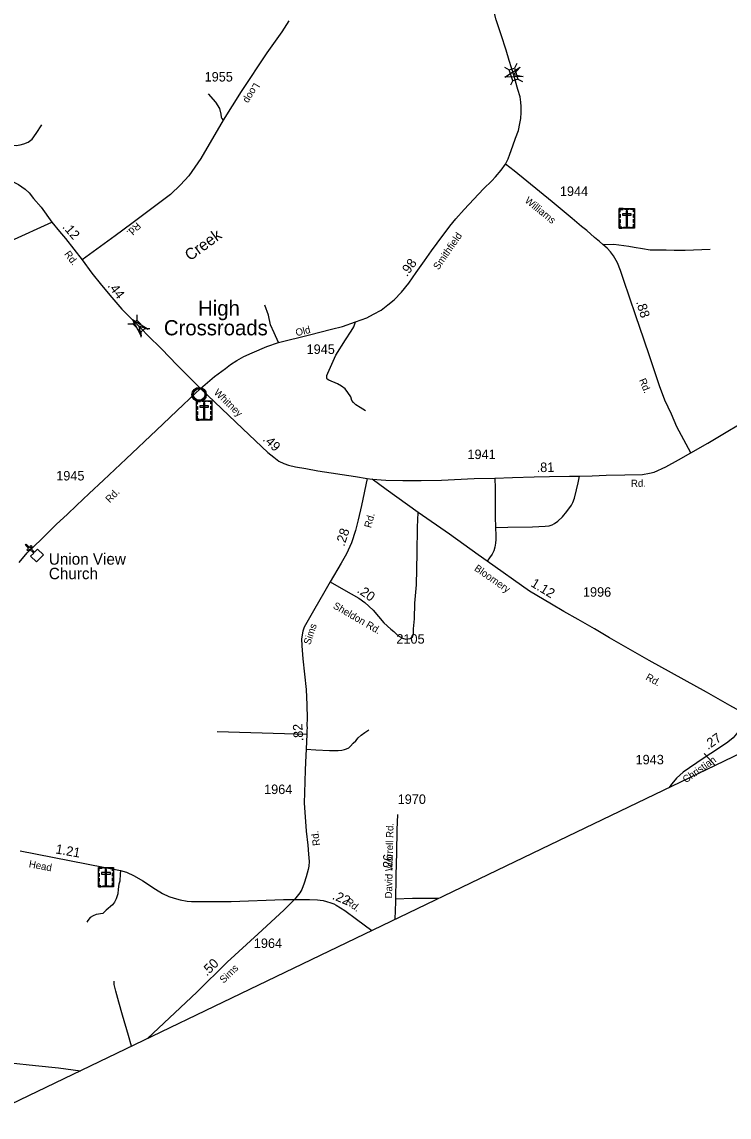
# Model space of a CAD drawing. Extents: x 2220236 to 2384410, y 720751 to 894131.
# Drawn here: x 2280691 to 2290003, y 740481 to 754902 of the extents above; entities that cross this region are included whole.
import ezdxf

# ---------------------------------------------------------------- set-up
doc = ezdxf.new("R2010")
doc.units = 0
doc.layers.add('Default', color=7, linetype='Continuous')

msp = doc.modelspace()

# ---------------------------------------------------------------- linework, layer by layer
at = {"layer": 'Default'}
for p, q in [((2287208, 754355), (2287177, 754294)), ((2287048, 754304), (2287109, 754272)), ((2287156, 754129), (2287124, 754067)), ((2287222, 754149), (2287283, 754118)), ((2282205, 751045), (2282204, 750976)), ((2282084, 750928), (2282153, 750927)), ((2282258, 750818), (2282256, 750749)), ((2282308, 750866), (2282377, 750865)), ((2285239, 748892), (2285304, 748879)), ((2289822, 745112), (2289673, 745271))]:
    msp.add_line(p, q, dxfattribs=at)
for points in [[(2287167, 754200), (2287109, 754392), (2287067, 754530), (2287001, 754731), (2286937, 754931), (2286870, 755191), (2286839, 755296), (2286815, 755396), (2286813, 755443), (2286806, 755503), (2286807, 755601), (2286821, 755780), (2286830, 755912), (2286851, 756119), (2286870, 756313), (2286881, 756471), (2286894, 756654), (2286896, 756785), (2286893, 756867), (2286868, 756978)], [(2284206, 754915), (2284114, 754770), (2283915, 754493), (2283577, 753984), (2283342, 753606), (2283049, 753103), (2282887, 752873), (2282780, 752756), (2282646, 752630), (2282140, 752249), (2281917, 752084), (2281486, 751771)], [(2287060, 753028), (2287094, 753101), (2287116, 753161), (2287156, 753269), (2287191, 753372), (2287229, 753470), (2287248, 753563), (2287261, 753630), (2287267, 753708), (2287265, 753790), (2287263, 753847), (2287250, 753917), (2287223, 754012), (2287167, 754200)], [(2283145, 753956), (2283242, 753845), (2283291, 753763), (2283309, 753687), (2283314, 753649), (2283324, 753628), (2283342, 753606)], [(2279960, 753282), (2280113, 753275), (2280189, 753286), (2280510, 753285), (2280616, 753276), (2280670, 753285), (2280718, 753295), (2280774, 753320), (2280824, 753358), (2280879, 753433), (2280954, 753547)], [(2279912, 753102), (2280529, 752822), (2280647, 752763), (2280736, 752699), (2280788, 752652), (2280842, 752575), (2280945, 752462), (2281085, 752263)], [(2283042, 750077), (2283228, 750231), (2283374, 750339), (2283440, 750391), (2283523, 750445), (2283613, 750497), (2283721, 750545), (2283918, 750627), (2284070, 750679), (2284479, 750782), (2284766, 750856), (2284914, 750892), (2285085, 750954), (2285231, 751004), (2285323, 751052), (2285423, 751106), (2285510, 751176), (2285592, 751242), (2285690, 751343), (2285784, 751463), (2285881, 751601), (2285993, 751755), (2286083, 751886), (2286161, 751988), (2286324, 752211), (2286405, 752309), (2286514, 752433), (2286770, 752704), (2286879, 752809), (2286926, 752860), (2287003, 752950), (2287060, 753028)], [(2289498, 749227), (2289317, 749571), (2289243, 749736), (2289155, 749922), (2289087, 750112), (2289027, 750295), (2288958, 750493), (2288880, 750725), (2288776, 751030), (2288694, 751277), (2288618, 751495), (2288574, 751629), (2288533, 751731), (2288479, 751820), (2288443, 751876), (2288399, 751924), (2288340, 751973), (2288296, 752009), (2288230, 752065), (2288131, 752154), (2288061, 752210), (2287937, 752314), (2287673, 752532), (2287171, 752943), (2287060, 753028)], [(2278224, 750919), (2278785, 751188), (2279193, 751386), (2280546, 752020), (2281085, 752263)], [(2281085, 752263), (2281184, 752142), (2281266, 752048), (2281486, 751771)], [(2288340, 751973), (2288485, 751975), (2288685, 751948), (2288755, 751938), (2288861, 751918), (2288965, 751901), (2289046, 751902), (2289174, 751900), (2289279, 751896), (2289423, 751898), (2289755, 751909)], [(2281486, 751771), (2281611, 751595), (2281740, 751435), (2281876, 751275), (2282009, 751118), (2282171, 750956), (2282265, 750860)], [(2284070, 750679), (2284014, 750806), (2283966, 750912), (2283938, 751042), (2283892, 751172)], [(2285215, 749783), (2285145, 749823), (2285090, 749860), (2285058, 749890), (2285036, 749916), (2285021, 749965), (2284985, 750023), (2284946, 750071), (2284900, 750104), (2284846, 750138), (2284731, 750183), (2284711, 750198), (2284705, 750212), (2284707, 750244), (2284719, 750278), (2284826, 750513), (2284954, 750717), (2285028, 750828), (2285063, 750886), (2285085, 750954)], [(2282265, 750860), (2282350, 750772), (2282528, 750599), (2282737, 750383), (2282952, 750167), (2283042, 750077)], [(2289498, 749227), (2289722, 749357), (2289923, 749475), (2290172, 749623), (2290408, 749756), (2290801, 749958), (2290961, 750056), (2291175, 750186), (2291342, 750283), (2291540, 750397), (2291661, 750471), (2291765, 750531), (2291859, 750573), (2291955, 750611), (2292119, 750666), (2292274, 750715)], [(2300140, 750264), (2297549, 748943), (2296605, 748443), (2294139, 747191), (2294129, 747181), (2290621, 745496), (2287877, 744178), (2270992, 736056), (2267562, 734406), (2264815, 733083), (2261891, 731668), (2260094, 730805), (2259694, 730607), (2256472, 729070), (2253954, 727878), (2253181, 727508), (2253078, 727457), (2253042, 727443), (2252978, 727424), (2252870, 727387), (2251763, 727086), (2250517, 726735), (2250148, 726626), (2248127, 726061)], [(2280656, 747785), (2280762, 747909), (2280948, 748092), (2281144, 748283), (2281293, 748422), (2281411, 748534), (2281576, 748691), (2281764, 748867), (2282065, 749149), (2282464, 749526), (2282820, 749866), (2283042, 750077)], [(2283042, 750077), (2283601, 749542), (2283930, 749233), (2284010, 749169), (2284075, 749120), (2284139, 749088), (2284201, 749066), (2284293, 749042), (2284428, 749020), (2284586, 748992), (2285083, 748916), (2285239, 748892)], [(2285304, 748879), (2285483, 748868), (2285709, 748862), (2285949, 748865), (2286215, 748869), (2286648, 748890), (2286919, 748896), (2287153, 748904), (2287438, 748910), (2287638, 748914), (2287902, 748920), (2288034, 748922), (2288201, 748926), (2288385, 748934), (2288631, 748936), (2288862, 748944), (2288956, 748960), (2289015, 748974), (2289169, 749044), (2289337, 749134), (2289498, 749227)], [(2285239, 748892), (2285162, 748534), (2285119, 748347), (2285085, 748203), (2285033, 748042), (2284965, 747899), (2284895, 747775), (2284750, 747528)], [(2290284, 745750), (2290015, 745902), (2289704, 746075), (2288953, 746493), (2288428, 746792), (2288232, 746910), (2288015, 747034), (2287828, 747137), (2287664, 747233), (2287377, 747407), (2286817, 747803), (2286700, 747886), (2286321, 748155), (2285909, 748443), (2285488, 748743), (2285304, 748879)], [(2286919, 748896), (2286921, 748762), (2286925, 748383), (2286929, 748243)], [(2286929, 748243), (2287088, 748249), (2287415, 748255), (2287581, 748263), (2287635, 748267), (2287673, 748279), (2287705, 748299), (2287749, 748327), (2287808, 748385), (2287866, 748457), (2287926, 748539), (2287944, 748575), (2287966, 748631), (2287994, 748742), (2288018, 748834), (2288034, 748922)], [(2285587, 746874), (2285643, 746824), (2285703, 746786), (2285747, 746774), (2285805, 746784), (2285834, 746806), (2285843, 746830), (2285847, 746854), (2285847, 746910), (2285859, 747042), (2285867, 747249), (2285885, 747489), (2285895, 747908), (2285901, 748247), (2285909, 748443)], [(2286929, 748243), (2286932, 748141), (2286930, 748088), (2286926, 748038), (2286920, 747984), (2286904, 747938), (2286882, 747892), (2286848, 747846), (2286817, 747803)], [(2284750, 747528), (2284680, 747405), (2284531, 747146), (2284443, 746993), (2284408, 746933), (2284391, 746881), (2284373, 746779), (2284378, 746688), (2284391, 746517), (2284433, 746112), (2284445, 745909), (2284447, 745730), (2284445, 745644), (2284447, 745604), (2284445, 745575), (2284441, 745523), (2284434, 745325), (2284431, 745244), (2284421, 745053), (2284417, 744897), (2284409, 744617), (2284419, 744435), (2284435, 744246), (2284455, 744061), (2284463, 743943), (2284473, 743848), (2284471, 743786), (2284461, 743740), (2284435, 743647), (2284407, 743563), (2284376, 743479), (2284352, 743436), (2284280, 743346)], [(2284750, 747528), (2284927, 747429), (2285126, 747313), (2285208, 747255), (2285318, 747155), (2285455, 746988), (2285551, 746906), (2285587, 746874)], [(2290284, 745750), (2290222, 745676), (2290164, 745606), (2290103, 745530), (2290055, 745477), (2289987, 745419), (2289863, 745333), (2289664, 745201), (2289398, 745021), (2289309, 744942), (2289271, 744898), (2289245, 744866), (2289216, 744821)], [(2283263, 745559), (2283704, 745547), (2284441, 745523)], [(2284434, 745325), (2284560, 745319), (2284740, 745309), (2284854, 745307), (2284903, 745311), (2284941, 745321), (2284967, 745329), (2284995, 745343), (2285019, 745367), (2285055, 745405), (2285087, 745437), (2285121, 745475), (2285159, 745509), (2285207, 745547), (2285259, 745579)], [(2285607, 743086), (2285616, 743316), (2285620, 743669), (2285628, 743962), (2285633, 744266), (2285643, 744466)], [(2280670, 743988), (2281988, 743730), (2282070, 743706), (2282169, 743659), (2282282, 743593), (2282451, 743481), (2282541, 743424), (2282625, 743386), (2282698, 743365), (2282774, 743340), (2282866, 743324), (2282926, 743318), (2283029, 743318), (2283121, 743318), (2283270, 743320), (2283448, 743322), (2284136, 743348), (2284192, 743346), (2284280, 743346)], [(2281988, 743730), (2281986, 743681), (2281984, 743651), (2281982, 743621), (2281979, 743586), (2281969, 743550), (2281960, 743484), (2281956, 743420), (2281933, 743356), (2281911, 743311), (2281886, 743277), (2281800, 743205), (2281767, 743172), (2281755, 743164), (2281667, 743149), (2281629, 743133), (2281590, 743109), (2281560, 743072), (2281544, 743048)], [(2284280, 743346), (2284206, 743272), (2284140, 743207), (2283803, 742894), (2283395, 742521), (2282995, 742127), (2282343, 741516)], [(2284280, 743346), (2284476, 743348), (2284582, 743343), (2284619, 743339), (2284658, 743333), (2284704, 743322), (2284759, 743304), (2284797, 743288), (2284831, 743270), (2284944, 743203), (2285098, 743089), (2285299, 742938)], [(2286176, 743361), (2285833, 743358), (2285611, 743350)], [(2282134, 741415), (2282095, 741555), (2282015, 741824), (2281967, 741996), (2281927, 742141), (2281906, 742227), (2281904, 742273)], [(2280541, 741195), (2280872, 741161), (2281172, 741130), (2281462, 741092)]]:
    msp.add_lwpolyline(points, dxfattribs=at)
for points in [[(2287292, 754184), (2287049, 754173), (2287254, 754304), (2287165, 754210)], [(2287177, 754294), (2287222, 754150), (2287155, 754128), (2287109, 754272)], [(2288557, 752443), (2288756, 752443), (2288756, 752188), (2288557, 752188)], [(2288557, 752399), (2288568, 752399), (2288568, 752432), (2288609, 752432), (2288609, 752443), (2288557, 752443)], [(2288557, 752325), (2288557, 752369), (2288568, 752369), (2288568, 752325)], [(2288598, 752375), (2288598, 752356), (2288715, 752356), (2288715, 752375)], [(2288631, 752443), (2288683, 752443), (2288683, 752431), (2288631, 752431)], [(2288666, 752413), (2288647, 752413), (2288647, 752211), (2288666, 752211)], [(2288756, 752399), (2288745, 752399), (2288745, 752432), (2288704, 752432), (2288704, 752443), (2288756, 752443)], [(2288744, 752326), (2288744, 752370), (2288756, 752370), (2288756, 752326)], [(2288557, 752258), (2288557, 752301), (2288568, 752301), (2288568, 752258)], [(2288590, 752188), (2288590, 752200), (2288568, 752200), (2288568, 752240), (2288557, 752240), (2288557, 752188)], [(2288614, 752200), (2288699, 752200), (2288699, 752188), (2288614, 752188)], [(2288723, 752188), (2288723, 752200), (2288745, 752200), (2288745, 752240), (2288756, 752240), (2288756, 752188)], [(2288744, 752260), (2288744, 752304), (2288756, 752304), (2288756, 752260)], [(2282261, 750769), (2282148, 750985), (2282354, 750855), (2282230, 750895)], [(2282204, 750976), (2282308, 750866), (2282257, 750818), (2282153, 750927)], [(2282948, 750008), (2282949, 750013), (2282950, 750020), (2282953, 750027), (2282956, 750033), (2282960, 750039), (2282963, 750044), (2282967, 750048), (2282972, 750053), (2282977, 750057), (2282983, 750061), (2282988, 750064), (2282993, 750066), (2282998, 750069), (2283004, 750070), (2283008, 750072), (2283013, 750072), (2283017, 750073), (2283024, 750073), (2283028, 750073), (2283034, 750073), (2283039, 750072), (2283044, 750071), (2283049, 750070), (2283054, 750068), (2283060, 750065), (2283067, 750061), (2283072, 750058), (2283077, 750054), (2283080, 750051), (2283084, 750046), (2283088, 750042), (2283091, 750037), (2283094, 750032), (2283097, 750027), (2283099, 750022), (2283100, 750017), (2283102, 750012), (2283103, 750006), (2283103, 750002), (2283104, 749996), (2283103, 749990), (2283103, 749984), (2283102, 749979), (2283100, 749972), (2283098, 749967), (2283096, 749962), (2283093, 749956), (2283090, 749950), (2283086, 749946), (2283082, 749941), (2283077, 749936), (2283072, 749932), (2283067, 749928), (2283062, 749926), (2283056, 749923), (2283048, 749920), (2283042, 749918), (2283036, 749917), (2283031, 749917), (2283027, 749916), (2283021, 749916), (2283017, 749917), (2283011, 749917), (2283006, 749919), (2283001, 749920), (2282996, 749922), (2282991, 749924), (2282987, 749926), (2282980, 749930), (2282975, 749935), (2282970, 749939), (2282966, 749944), (2282962, 749948), (2282959, 749952), (2282955, 749959), (2282954, 749963), (2282952, 749967), (2282949, 749975), (2282948, 749982), (2282947, 749987), (2282947, 749993), (2282947, 749998), (2282947, 750005)], [(2282991, 749914), (2283190, 749914), (2283190, 749660), (2282991, 749660)], [(2282991, 749871), (2283002, 749871), (2283002, 749903), (2283043, 749903), (2283043, 749914), (2282991, 749914)], [(2283065, 749914), (2283117, 749914), (2283117, 749903), (2283065, 749903)], [(2283100, 749885), (2283081, 749885), (2283081, 749682), (2283100, 749682)], [(2283190, 749871), (2283179, 749871), (2283179, 749903), (2283138, 749903), (2283138, 749914), (2283190, 749914)], [(2282991, 749797), (2282991, 749840), (2283002, 749840), (2283002, 749797)], [(2282991, 749729), (2282991, 749773), (2283002, 749773), (2283002, 749729)], [(2283032, 749846), (2283032, 749827), (2283149, 749827), (2283149, 749846)], [(2283179, 749798), (2283179, 749841), (2283190, 749841), (2283190, 749798)], [(2283179, 749732), (2283179, 749775), (2283190, 749775), (2283190, 749732)], [(2283024, 749660), (2283024, 749671), (2283002, 749671), (2283002, 749711), (2282991, 749711), (2282991, 749660)], [(2283048, 749671), (2283133, 749671), (2283133, 749660), (2283048, 749660)], [(2283157, 749660), (2283157, 749671), (2283179, 749671), (2283179, 749711), (2283190, 749711), (2283190, 749660)], [(2280806, 747866), (2280846, 747907), (2280792, 747960), (2280769, 747937), (2280758, 747949), (2280780, 747972), (2280737, 748014), (2280748, 748025), (2280791, 747983), (2280814, 748006), (2280825, 747995), (2280803, 747972), (2280857, 747919), (2280898, 747960), (2280974, 747886), (2280883, 747792)], [(2281698, 743769), (2281897, 743769), (2281897, 743514), (2281698, 743514)], [(2281698, 743726), (2281709, 743726), (2281709, 743758), (2281750, 743758), (2281750, 743769), (2281698, 743769)], [(2281698, 743651), (2281698, 743695), (2281709, 743695), (2281709, 743651)], [(2281738, 743701), (2281738, 743682), (2281856, 743682), (2281856, 743701)], [(2281772, 743769), (2281824, 743769), (2281824, 743758), (2281772, 743758)], [(2281807, 743740), (2281788, 743740), (2281788, 743537), (2281807, 743537)], [(2281897, 743726), (2281885, 743726), (2281885, 743758), (2281845, 743758), (2281845, 743769), (2281897, 743769)], [(2281885, 743652), (2281885, 743696), (2281897, 743696), (2281897, 743652)], [(2281698, 743584), (2281698, 743628), (2281709, 743628), (2281709, 743584)], [(2281731, 743514), (2281731, 743526), (2281709, 743526), (2281709, 743566), (2281698, 743566), (2281698, 743514)], [(2281755, 743526), (2281840, 743526), (2281840, 743514), (2281755, 743514)], [(2281864, 743514), (2281864, 743526), (2281886, 743526), (2281886, 743566), (2281897, 743566), (2281897, 743514)], [(2281885, 743587), (2281885, 743630), (2281897, 743630), (2281897, 743587)]]:
    msp.add_lwpolyline(points, close=True, dxfattribs=at)
for centre, radius in [((2283025, 749995), 94.3), ((2283025, 749996), 76.7)]:
    msp.add_circle(centre, radius, dxfattribs=at)

# ---------------------------------------------------------------- texts
for s, height, p in [('1955', 125, (2283097, 754117)), ('1944', 125, (2287775, 752610)), ('      High', 200, (2282565, 751033)), ('Crossroads', 200, (2282561, 750775)), ('1945', 125, (2284440, 750530)), ('1941', 125, (2286558, 749146)), ('1945', 125, (2281143, 748864)), ('Union View', 150, (2281046, 747755)), ('Church', 150, (2281046, 747564)), ('1996', 125, (2288079, 747333)), ('2105', 125, (2285622, 746715)), ('1943', 125, (2288772, 745126)), ('1964', 125, (2283880, 744735)), ('1970', 125, (2285639, 744605)), ('1964', 125, (2283745, 742708))]:
    msp.add_text(s, height=height, dxfattribs=at).set_placement(p)
for s, height, rotation, p in [('Loop', 95, 239.1779, (2283750, 754107)), ('Williams', 95, 321.049, (2287305, 752534)), ('.12', 125, 311.0814, (2281218, 752199)), ('Rd.', 95, 223.0376, (2282204, 752271)), ('Creek', 150, 36.3699, (2282905, 751748)), ('Smithfield', 95, 55.4886, (2286177, 751629)), ('Rd.', 95, 306.6983, (2281244, 751845)), ('.98', 125, 53.8008, (2285761, 751540)), ('.44', 125, 307.5135, (2281814, 751426)), ('.88', 125, 287.1316, (2288777, 751215)), ('Old', 95, 13.7412, (2284306, 750762)), ('Rd.', 95, 292.3904, (2288815, 750186)), ('Whitney', 95, 316.2202, (2283212, 750012)), ('.49', 125, 316.5461, (2283855, 749396)), ('.81', 125, 1.1464, (2287470, 748973)), ('Rd.', 95, 1.0314, (2288712, 748778)), ('Rd.', 95, 45.6967, (2281848, 748563)), ('Rd.', 95, 74.8015, (2285287, 748232)), ('.28', 125, 72.0067, (2284936, 747989)), ('Bloomery', 95, 325.1849, (2286639, 747686)), ('1.12', 125, 328.8448, (2287382, 747477)), ('.20', 125, 324.7109, (2285095, 747398)), ('Sheldon Rd.', 95, 329.8704, (2284779, 747188)), ('Sims', 95, 71.5, (2284487, 746693)), ('Rd.', 95, 330.3776, (2288896, 746247)), ('.82', 125, 94.054, (2284398, 745433)), ('.27', 125, 34.7603, (2289725, 745313)), ('Christian', 95, 35.2244, (2289433, 744876)), ('Rd.', 95, 97.1963, (2284617, 744060)), ('David Worrell Rd.', 95, 88.8537, (2285565, 743359)), ('1.21', 125, 349.9382, (2281128, 743954)), ('Head', 95, 349.7053, (2280777, 743771)), ('.26', 125, 88.4736, (2285568, 743713)), ('.22', 125, 336.998, (2284769, 743356)), ('Rd.', 95, 322.7391, (2284945, 743300)), ('.50', 125, 44.5112, (2283127, 742330)), ('Sims', 95, 44.1957, (2283348, 742237))]:
    msp.add_text(s, height=height, rotation=rotation, dxfattribs=at).set_placement(p)

doc.saveas('drawing.dxf')
